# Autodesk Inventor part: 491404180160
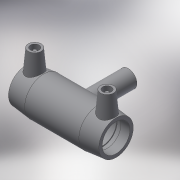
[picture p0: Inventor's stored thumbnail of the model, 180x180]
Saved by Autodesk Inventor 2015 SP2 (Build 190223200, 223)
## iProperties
Created: 2017-06
Part Number: 491404180160
Material: Generic
Description: PLASSON REDUCING TEE 180x160x180
Document SubType Name: Modeling
Designer: KIM
Mass: 57.3761 g
Surface Area: 241.06 cm^2
Volume: 57.3761 cm^3
Density: 1 g/cm^3
Appearance: Default
Author: KIM
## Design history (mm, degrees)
derived "491404.ipt"
feature "Solid1::491404.ipt"
tag "TaggingFeature1"
body "Solid1"
other parameters: "d0" = 422, "d2" = 245, "d3" = 106, "d4" = 84.4, "d5" = 220.5, "d6" = 171, "d8" = 168 deg, "d10" = 42.4, "d11" = 14.13333, "d13" = 422, "d14" = 17.6296, "d17" = 162, "d19" = 3.52592, "d20" = 168 deg, "d22" = 227.85, "d23" = 245, "d25" = 135 deg, "d26" = 295.4, "d29" = 116, "d30" = 15, "d31" = 168.8, "d34" = 5 deg, "d35" = 15, "d39" = 5 deg, "d41" = 4, "d42" = 14, "d43" = 0, "d45" = 4, "d46" = 6, "d47" = 0, "d51" = 0, "d52" = 128, "d54" = 0, "d55" = 220.5, "d56" = 245, "d57" = 147.7, "d58" = 135 deg, "d59" = 106, "d60" = 106, "d61" = 135 deg, "d72" = 192.01, "d73" = 96.005, "d75" = 168, "d77" = 0, "d78" = 128, "d80" = 0, "d82" = 127.5, "d83" = 0, "d84" = 3, "d85" = 0, "d86" = 35.33333, "d87" = 223.293, "d88" = 14.13333, "d89" = 3, "d90" = 0, "L_" = 422, "L_1" = 106, "D_" = 245, "A_" = 116, "d_2" = 12
